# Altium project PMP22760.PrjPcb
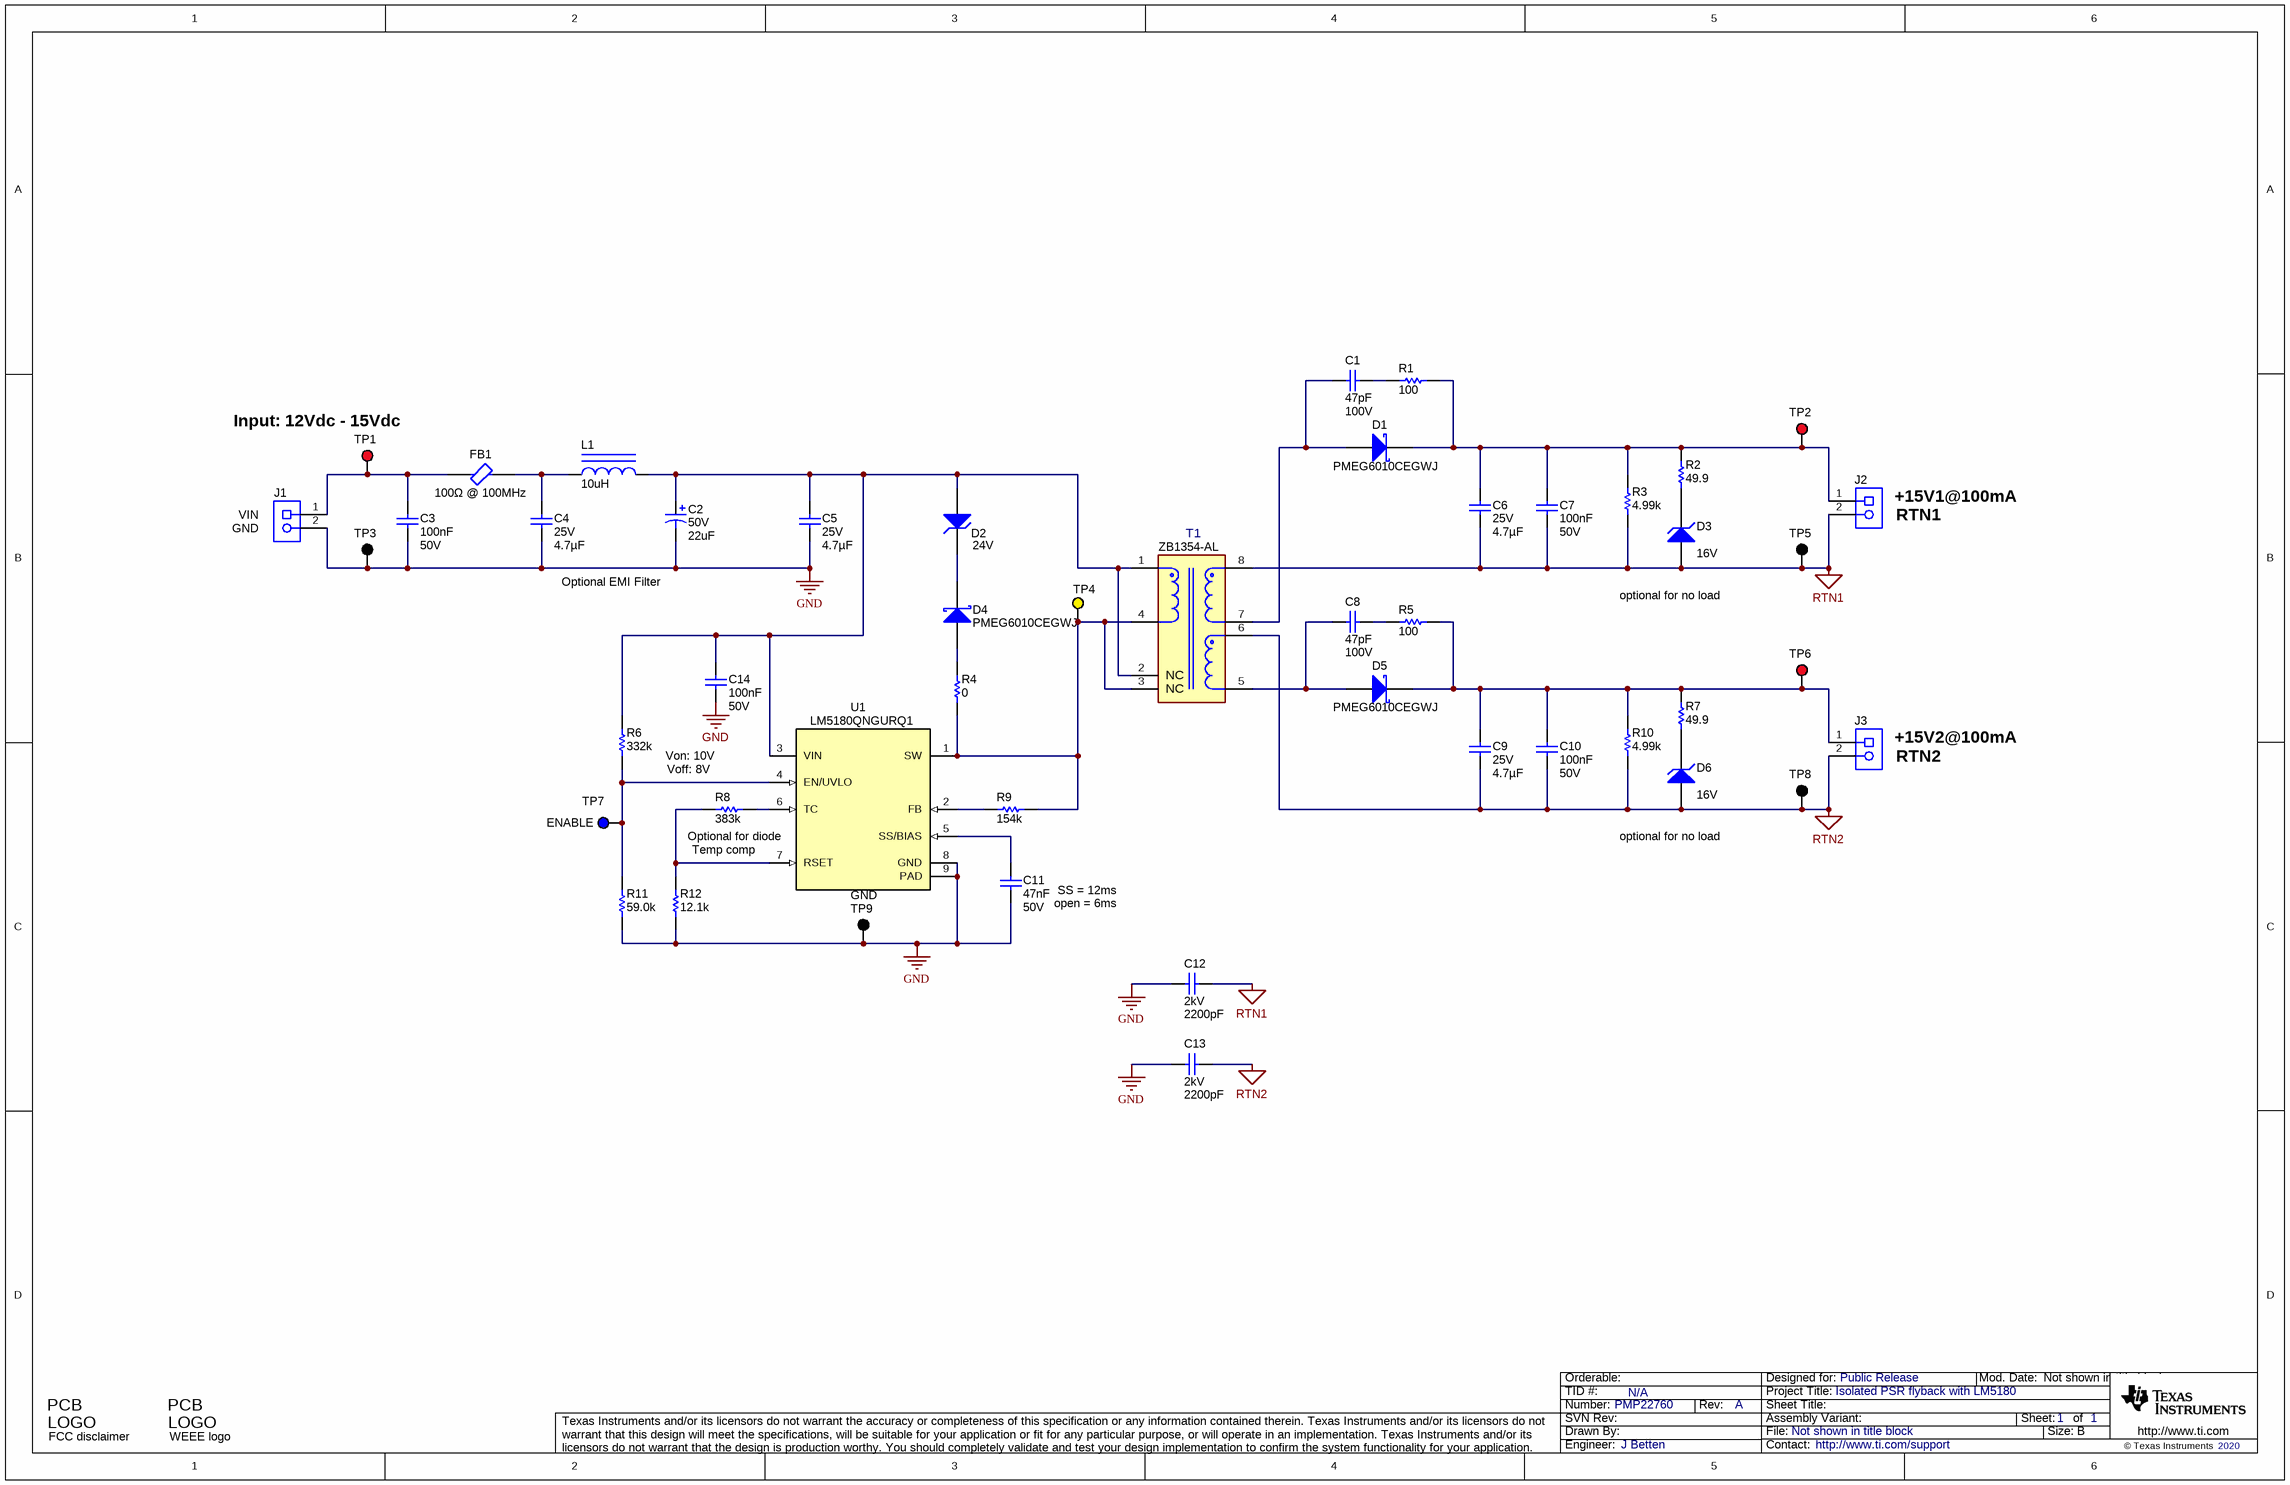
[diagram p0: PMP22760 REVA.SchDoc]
CopyrightYear: 2020; PCB_Layout: J Betten; PCB_Rev: A; PRJ_Customer: Public Release; PRJ_Engineer: J Betten; PRJ_Number: PMP22760; PRJ_Title: Isolated PSR flyback with LM5180; SCH_Rev: A; TechSupport: http://www.ti.com/support; TID: N/A
1 sheet, 50 parts. Net scope: global (net labels, ports and power ports of the same name join across sheets).
Board file: PMP22760_PCB.PcbDoc

## Sheet PMP22760 REVA.SchDoc
size 431 x 279 mm; Date: Not shown in title block; ApprovedBy: Not shown in title block; CheckedBy: Not shown in title block; Author: Not shown in title block; CompanyName: Not shown in title block; Engineer: Not shown in title block; Organization: Not shown in title block; Address1: Not shown in title block; Address2: Not shown in title block; Address3: Not shown in title block; Address4: Not shown in title block; DocumentNumber: 1; Revision: Use project parameter SCH_Rev; SheetNumber: 1; SheetTotal: 1; PageSetup: Record=PageOptions¦CenterHorizontal=True¦CenterVertical=True¦PrintScale=1.00¦XCorrection=1.00¦YCorrection=1.00¦PrintKind=0¦BorderSize=5000000¦LeftOffset=0¦BottomOffset=0¦Orientation=2¦PaperLength=1000¦PaperWidth=1000¦Scale=100¦PaperSource=15¦PrintQuality=600¦MediaType=1¦DitherType=10¦PaperKind=Letter¦PrintScaleMode=1

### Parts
C1  ValueDisplayed: 47pF  VDC_V: 100V  [0603]  (hidden comment: C0603C470J1GACAUTO)
C2  VDC_V: 50V  ValueDisplayed: 22uF  [SM_RADIAL_D]  (hidden comment: EEE-FK1H220P)
C3  Cap_F: 100nF  VDC_V: 50V  [0603]  (hidden comment: CGA3E2X7R1H104K080AA)
C4  VDC_V: 25V  ValueDisplayed: 4.7µF  [1206_180]  (hidden comment: GCM31CR71E475KA55L)
C5  VDC_V: 25V  ValueDisplayed: 4.7µF  [1206_180]  (hidden comment: GCM31CR71E475KA55L)
C6  VDC_V: 25V  ValueDisplayed: 4.7µF  [1206_180]  (hidden comment: GCM31CR71E475KA55L)
C7  Cap_F: 100nF  VDC_V: 50V  [0603]  (hidden comment: CGA3E2X7R1H104K080AA)
C8  ValueDisplayed: 47pF  VDC_V: 100V  [0603]  (hidden comment: C0603C470J1GACAUTO)
C9  VDC_V: 25V  ValueDisplayed: 4.7µF  [1206_180]  (hidden comment: GCM31CR71E475KA55L)
C10  Cap_F: 100nF  VDC_V: 50V  [0603]  (hidden comment: CGA3E2X7R1H104K080AA)
C11  Cap_F: 47nF  VDC_V: 50V  [0603]  (hidden comment: CGA3E2X7R1H473K080AA)
C12  VDC_V: 2kV  ValueDisplayed: 2200pF  [1206_180]  (hidden comment: 1206J2K00222KXR)
C13  VDC_V: 2kV  ValueDisplayed: 2200pF  [1206_180]  (hidden comment: 1206J2K00222KXR)
C14  Cap_F: 100nF  VDC_V: 50V  [0603]  (hidden comment: CGA3E2X7R1H104K080AA)
D1  PMEG6010CEGWJ  [SOD-123]
D2  value 24V  [SOD-123]  (hidden comment: MMSZ5252BT1G)
D3  value 16V  [SOD-123]  (hidden comment: MMSZ4703-HE3-08)
D4  PMEG6010CEGWJ  [SOD-123]
D5  PMEG6010CEGWJ  [SOD-123]
D6  value 16V  [SOD-123]  (hidden comment: MMSZ4703-HE3-08)
FB1  Impedance At Frequency: 100Ω @ 100MHz  [FP-MPZ2012S101ATD25_0805-MFG]  (hidden comment: MPZ2012S101ATD25)
J1  0393570002  [MOLEX_39357-0002]  (value not drawn)
J2  0393570002  [MOLEX_39357-0002]  (value not drawn)
J3  0393570002  [MOLEX_39357-0002]  (value not drawn)
L1  ValueDisplayed: 10uH  [WE-TPC-M1]  (hidden comment: 744042100)
Logo1  FCC disclaimer  [FCC_disclaimer]  (no BOM)
Logo2  WEEE logo  [WEEE_Minimum]  (no BOM)
R1  ValueDisplayed: 100  [0805_HV]  (hidden comment: CRCW0805100RJNEA)
R2  ValueDisplayed: 49.9  [0805_HV]  (hidden comment: CRCW080549R9FKEA)
R3  ValueDisplayed: 4.99k  [0805_HV]  (hidden comment: CRCW08054K99FKEA)
R4  ValueDisplayed: 0  [0603]  (hidden comment: CRCW06030000Z0EA)
R5  ValueDisplayed: 100  [0805_HV]  (hidden comment: CRCW0805100RJNEA)
R6  ValueDisplayed: 332k  [0603]  (hidden comment: CRCW0603332KFKEA)
R7  ValueDisplayed: 49.9  [0805_HV]  (hidden comment: CRCW080549R9FKEA)
R8  ValueDisplayed: 383k  [0603]  (hidden comment: CRCW0603383KFKEA)
R9  ValueDisplayed: 154k  [0603]  (hidden comment: CRCW0603154KFKEA)
R10  ValueDisplayed: 4.99k  [0805_HV]  (hidden comment: CRCW08054K99FKEA)
R11  ValueDisplayed: 59.0k  [0603]  (hidden comment: CRCW060359K0FKEA)
R12  ValueDisplayed: 12.1k  [0603]  (hidden comment: CRCW060312K1FKEA)
T1  ZB1354-AL  [FP-ZB1354-AL_SMT8_9MM3_10MM2-MFG]
TP1  5000  [Keystone5000]  (value not drawn)
TP2  5000  [Keystone5000]  (value not drawn)
TP3  (no value)  [Keystone5001]
TP4  SW  [Keystone5004]  (value not drawn)
TP5  (no value)  [Keystone5001]
TP6  5000  [Keystone5000]  (value not drawn)
TP7  EN  [Keystone5117]  (value not drawn)
TP8  (no value)  [Keystone5001]
TP9  GND  [Keystone5001]
U1  LM5180QNGURQ1  [NGU0008C]

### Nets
GND: C2.2(-) C3.2 C4.2 C5.2 C11.2 C12.2 C13.2 C14.2 J1.2(Vin) R11.1 R12.1 TP3.1 TP9.1 U1.8(GND) U1.9(PAD)
RTN1: C6.2 C7.2 C12.1 D3.2(A) J2.2(V12) R3.1 T1.8 TP5.1
RTN2: C9.2 C10.2 C13.1 D6.2(A) J3.2(V12) R10.1 T1.6 TP8.1
NetC1_1: C1.1 R1.1
NetC1_2: C1.2 D1.2(A) T1.7
NetC2_1: C2.1(+) C5.1 C14.1 D2.2(A) L1.2 R6.2 T1.1 T1.2(NC) U1.3(VIN)
NetC3_1: C3.1 FB1.1 J1.1(GND) TP1.1
NetC4_1: C4.1 FB1.2 L1.1
NetC6_1: C6.1 C7.1 D1.1(K) J2.1(V11) R1.2 R2.2 R3.2 TP2.1
NetC8_1: C8.1 R5.1
NetC8_2: C8.2 D5.2(A) T1.5
NetC9_1: C9.1 C10.1 D5.1(K) J3.1(V11) R5.2 R7.2 R10.2 TP6.1
NetC11_1: C11.1 U1.5(SS/BIAS)
NetD2_1: D2.1(K) D4.1(K)
NetD3_1: D3.1(K) R2.1
NetD4_2: D4.2(A) R4.2
NetD6_1: D6.1(K) R7.1
NetR4_1: R4.1 R9.2 T1.3(NC) T1.4 TP4.1 U1.1(SW)
NetR6_1: R6.1 R11.2 TP7.1 U1.4(EN/UVLO)
NetR8_1: R8.1 R12.2 U1.7(RSET)
NetR8_2: R8.2 U1.6(TC)
NetR9_1: R9.1 U1.2(FB)

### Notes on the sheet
- (near TP1) Input: 12Vdc - 15Vdc
- (near J2) +15V1@100mA
- (near J1) VIN
- (near J1) GND
- (near J2) RTN1
- Optional EMI Filter
- optional for no load
- Voff: 8V
- Von: 10V
- (near J3) +15V2@100mA
- (near J3) RTN2
- (near TP7) ENABLE
- Optional for diode
- Temp comp
- (near C11) SS = 12ms
- (near C11) open = 6ms

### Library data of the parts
C1 C8 = CMP-0085572-1: CAP, CERM, 47 pF, 100 V,+/- 5%, C0G/NP0, AEC-Q200 Grade 1, 0603; Manufacturer: Kemet; TaMax_C: 125°C; AEC Category: Q200; AEC Grade: 1; TaMin_C: -55°C; SizeArea_mm2: 1.28; Value: 47pF; AEC Qualified: Y; Polarized: N; SizeX_mm: 1.6; U/M: EA; SizeY_mm: 0.8; SizeAreaWB_mm2: 4.68
C2 = CMP-0011179-2: CAP, AL, 22 uF, 50 V, +/- 20%, 0.88 ohm, AEC-Q200 Grade 2, SMD; Manufacturer: Panasonic; TaMin_C: -55°C; ESR_ohm: 0.88; Polarized: Y; SizeAreaWB_mm2: 84.28; U/M: EA; Value: 22uF; TaMax_C: 105°C; SizeZ_mm: 5.4; SizeX_mm: 7.8; SizeY_mm: 6.6; Cap_Case: D; SizeArea_mm2: 51.48; CompType: Capacitor; Cap_F: 22µF; IRMS_A: 165mA; AEC Grade: 2; AEC Category: Q200
C3 C7 C10 C14 = CMP-0007078-4: CAP, CERM, 0.1 uF, 50 V, +/- 10%, X7R, AEC-Q200 Grade 1, 0603; Manufacturer: TDK; TaMin_C: -55°C; ESR_ohm: 0.0296; Polarized: N; SizeAreaWB_mm2: 4.68; Value1: 0.0296 ohm; U/M: EA; Value: 0.1uF; TaMax_C: 125°C; SizeZ_mm: 1; SizeX_mm: 1.6; SizeY_mm: 0.8; SizeArea_mm2: 1.28; AEC Qualified: Y; IRMS_A: 971.99mA; AEC Category: Q200
C4-C6 C9 = CMP-0082300-1: CAP, CERM, 4.7 µF, 25 V,+/- 10%, X7R, AEC-Q200 Grade 1, 1206; Manufacturer: MuRata; SizeAreaWB_mm2: 10.92; SizeArea_mm2: 5.12; AEC Qualified: Y; AEC Category: Q200; Value: 4.7uF; TaMax_C: 125°C; SizeZ_mm: 1.8; AEC Grade: 1; Polarized: N; TaMin_C: -55°C; SizeY_mm: 1.6; U/M: EA; SizeX_mm: 3.2; Cap_Case: 1206
C11 = CMP-0007079-4: CAP, CERM, 0.047 uF, 50 V, +/- 10%, X7R, AEC-Q200 Grade 1, 0603; Manufacturer: TDK; TaMin_C: -55°C; ESR_ohm: 0.049007; Polarized: N; SizeAreaWB_mm2: 4.68; Value1: 0.049007 ohm; U/M: EA; TaMax_C: 125°C; SizeZ_mm: 1; SizeX_mm: 1.6; SizeY_mm: 0.8; SizeArea_mm2: 1.28; AEC Qualified: Y; IRMS_A: 767.528mA; AEC Category: Q200
C12 C13 = CMP-0077201-1: CAP, CERM, 2200 pF, 2000 V,+/- 10%, X7R, AEC-Q200 Grade 1, 1206; Manufacturer: Knowles Capacitors; TaMin_C: -55°C; Polarized: N; SizeAreaWB_mm2: 10.92; U/M: EA; Value: 2200pF; TaMax_C: 125°C; SizeZ_mm: 1.8; SizeX_mm: 3.2; SizeY_mm: 1.6; Cap_Case: 1206; Value2: 2000V; SizeArea_mm2: 5.12; AEC Qualified: Y; Cap_F: 2.2nF; AEC Grade: 1; AEC Category: Q200
D1 D4 D5 = CMP-0079239-2: Diode, Schottky, 60 V, 1 A, AEC-Q101, SOD-123; Manufacturer: Nexperia; SizeY_mm: 1.7; AEC Qualified: Y; SizeArea_mm2: 6.545; Vf_V: 660mV; Value: 60V; Value1: 1A; AEC Category: Q101; TJmax_C: 150°C; SizeX_mm: 3.85; SizeZ_mm: 1.35; SizeAreaWB_mm2: 13.095; Value2: 0.66V
D2 = CMP-0005771-4: Diode, Zener, 24 V, 500 mW, AEC-Q101, SOD-123; Manufacturer: ON Semiconductor; Power_W: 500mW; SizeY_mm: 1.7; SizeAreaWB_mm2: 13.095; SizeX_mm: 3.85; RJA_CperW: 340; AEC Category: Q101; SizeArea_mm2: 6.545; AEC Qualified: Y; SizeZ_mm: 1.35; Value1: 0.5W
D3 D6 = CMP-0077576-3: Diode, Zener, 16 V, 500 mW, AEC-Q101, SOD-123; Manufacturer: Vishay-Semiconductor; Power_W: 500mW; RJA_CperW: 340; SizeAreaWB_mm2: 13.095; SizeX_mm: 3.85; AEC Category: Q101; Value1: 0.5W; AEC Qualified: Y; SizeArea_mm2: 6.545; SizeZ_mm: 1.35; SizeY_mm: 1.7
FB1 = CMP-0089947-1: 100 Ohms @ 100MHz 1 Power Line Ferrite Bead 0805 (2012 Metric) 4A 20mOhm; Manufacturer: TDK; AEC Qualified: Yes; AEC Grade: Grade 1; DCR_ohm: 0.02; Tolerance_%: 25%; SizeZ_mm: 1.05mm
J1-J3 = CMP-0055341-2: Terminal Block, 3.5 mm, 2x1, Tin, TH; Manufacturer: Molex; CNHeader: FALSE; CT: TRUE; Green_Lifecycle: Not Set; Green_REACh: Incomplete
L1 = CMP-0063804-1: Inductor, Shielded Drum Core, Ferrite, 10 uH, 1 A, 0.12 ohm, SMD; Manufacturer: Wurth Elektronik; Isat: 1A @ 35% inductance drop; Irms: 1.3A @ 30C rise; Green_Lifecycle: Active; SizeAreaWB_mm2: 33.64; DCR_ohm: 0.12; Green_REACh: Passed; Value: 10uH; Imax_A: 1A; SizeZ_mm: 1.8; SizeX_mm: 4.8; SizeArea_mm2: 23.04; Ind_H: 10µH; AEC Category: Q200
Logo1 = CMP-0074847-1: FCC_disclaimer; Library Reference: Logo
Logo2 = CMP-0074769-1
R1 R5 = CMP-0020445-3: RES, 100, 5%, 0.125 W, AEC-Q200 Grade 0, 0805; Manufacturer: Vishay-Dale; Power_W: 125mW; TempCo: 200 ppm/C; Value_Code: 100R; Value: 100; EIA_Code: E24; SizeX_mm: 2; SizeY_mm: 1.25; SizeZ_mm: 1.45; Value2: 0.125W; SizeArea_mm2: 2.5; AEC Qualified: Y; VDC_V: 150V; AEC Category: Q200; AEC Grade: 0
R2 R7 = CMP-0021284-3: RES, 49.9, 1%, 0.125 W, AEC-Q200 Grade 0, 0805; Manufacturer: Vishay-Dale; Power_W: 125mW; TempCo: 100 ppm/C; Value_Code: 49R9; Value: 49.9; EIA_Code: E96; SizeX_mm: 2; SizeY_mm: 1.25; SizeZ_mm: 1.45; Value2: 0.125W; SizeArea_mm2: 2.5; AEC Qualified: Y; VDC_V: 150V; AEC Category: Q200; AEC Grade: 0
R3 R10 = CMP-0021294-3: RES, 4.99 k, 1%, 0.125 W, AEC-Q200 Grade 0, 0805; Manufacturer: Vishay-Dale; Power_W: 125mW; TempCo: 100 ppm/C; Value_Code: 4k99; Value: 4.99k; EIA_Code: E96; SizeX_mm: 2; SizeY_mm: 1.25; SizeZ_mm: 1.45; Value2: 0.125W; SizeArea_mm2: 2.5; AEC Qualified: Y; VDC_V: 150V; AEC Category: Q200; AEC Grade: 0
R4 = CMP-0025697-4: RES, 0, 5%, 0.1 W, AEC-Q200 Grade 0, 0603; Manufacturer: Vishay-Dale; Power_W: 100mW; TempCo: 200 ppm/C; Value_Code: 0000; Value: 0; EIA_Code: E24; SizeX_mm: 1.6; SizeY_mm: 0.8; SizeZ_mm: 1; Value2: 0.1W; SizeArea_mm2: 1.28; AEC Qualified: Y; VDC_V: 75V; AEC Category: Q200
R6 = CMP-0022336-4: RES, 332 k, 1%, 0.1 W, AEC-Q200 Grade 0, 0603; Manufacturer: Vishay-Dale; Power_W: 100mW; TempCo: 100 ppm/C; Value: 332k; EIA_Code: E96; SizeX_mm: 1.6; SizeY_mm: 0.8; SizeZ_mm: 1; Value2: 0.1W; SizeArea_mm2: 1.28; AEC Qualified: Y; VDC_V: 75V; AEC Category: Q200; AEC Grade: 0
R8 = CMP-0022362-4: RES, 383 k, 1%, 0.1 W, AEC-Q200 Grade 0, 0603; Manufacturer: Vishay-Dale; Power_W: 100mW; TempCo: 100 ppm/C; Value: 383k; EIA_Code: E96; SizeX_mm: 1.6; SizeY_mm: 0.8; SizeZ_mm: 1; Value2: 0.1W; SizeArea_mm2: 1.28; AEC Qualified: Y; VDC_V: 75V; AEC Category: Q200; AEC Grade: 0
R9 = CMP-0022062-4: RES, 154 k, 1%, 0.1 W, AEC-Q200 Grade 0, 0603; Manufacturer: Vishay-Dale; Power_W: 100mW; TempCo: 100 ppm/C; Value: 154k; EIA_Code: E96; SizeX_mm: 1.6; SizeY_mm: 0.8; SizeZ_mm: 1; Value2: 0.1W; SizeArea_mm2: 1.28; AEC Qualified: Y; VDC_V: 75V; AEC Category: Q200; AEC Grade: 0
R11 = CMP-0022507-4: RES, 59.0 k, 1%, 0.1 W, AEC-Q200 Grade 0, 0603; Manufacturer: Vishay-Dale; Power_W: 100mW; TempCo: 100 ppm/C; Value_Code: 59k0; Value: 59.0k; EIA_Code: E96; Res_ohm: 59k; SizeX_mm: 1.6; SizeY_mm: 0.8; SizeZ_mm: 1; Value2: 0.1W; SizeArea_mm2: 1.28; AEC Qualified: Y; VDC_V: 75V; AEC Category: Q200; AEC Grade: 0
R12 = CMP-0022030-4: RES, 12.1 k, 1%, 0.1 W, AEC-Q200 Grade 0, 0603; Manufacturer: Vishay-Dale; Power_W: 100mW; TempCo: 100 ppm/C; Value_Code: 12k1; Value: 12.1k; EIA_Code: E96; SizeX_mm: 1.6; SizeY_mm: 0.8; SizeZ_mm: 1; Value2: 0.1W; SizeArea_mm2: 1.28; AEC Qualified: Y; VDC_V: 75V; AEC Category: Q200; AEC Grade: 0
T1 = CMP-0090909-2: FLYBACK TRANSFORMER SMD 8 Pin 10-16Vin 200-350kHz, Output 15.7/.185A x 2 Turns Ratio 1:1:1; Manufacturer: Coilcraft; AEC Qualified: No; Ind_H: 27µH; SizeZ_mm: 10.6mm; Voltage_Isolation_Vrms: 1500Vrms; DCR_ohm: 0.075
TP1 TP2 TP6 = CMP-0055137-1: Test Point, Miniature, Red, TH; Manufacturer: Keystone; CNHeader: FALSE; Green_Lifecycle: Active; Green_REACh: Passed; ContactFinish: Silver; CT: TRUE
TP3 TP5 TP8 TP9 = CMP-0055138-1: Test Point, Miniature, Black, TH; Manufacturer: Keystone; CNHeader: FALSE; Green_Lifecycle: Active; Green_REACh: Passed; ContactFinish: Silver; CT: TRUE
TP4 = CMP-0055141-1: Test Point, Miniature, Yellow, TH; Manufacturer: Keystone; CNHeader: FALSE; Green_Lifecycle: Active; Green_REACh: Passed; ContactFinish: Silver; CT: TRUE
TP7 = CMP-0055154-1: Test Point, Miniature, Blue, TH; Manufacturer: Keystone; CNHeader: FALSE; Green_Lifecycle: Active; Green_REACh: Passed; ContactFinish: Silver; CT: TRUE
U1 = CMP-0078633-2: 70-V PSR Flyback Converter With 100-V, 1.2-A Power Switch and Ultra-Low IQ, NGU0008C (WSON-8); Alternate PartNumber: LM5180QNGUTQ1; Alternate Manufacturer: Texas Instruments; SizeAreaWB_mm2: 25; SizeZ_mm: 0.8; SizeX_mm: 4; SizeArea_mm2: 16; CompType: IC; AEC Qualified: Y; AEC Category: Q200

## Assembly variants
001: not fitted R3 R10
